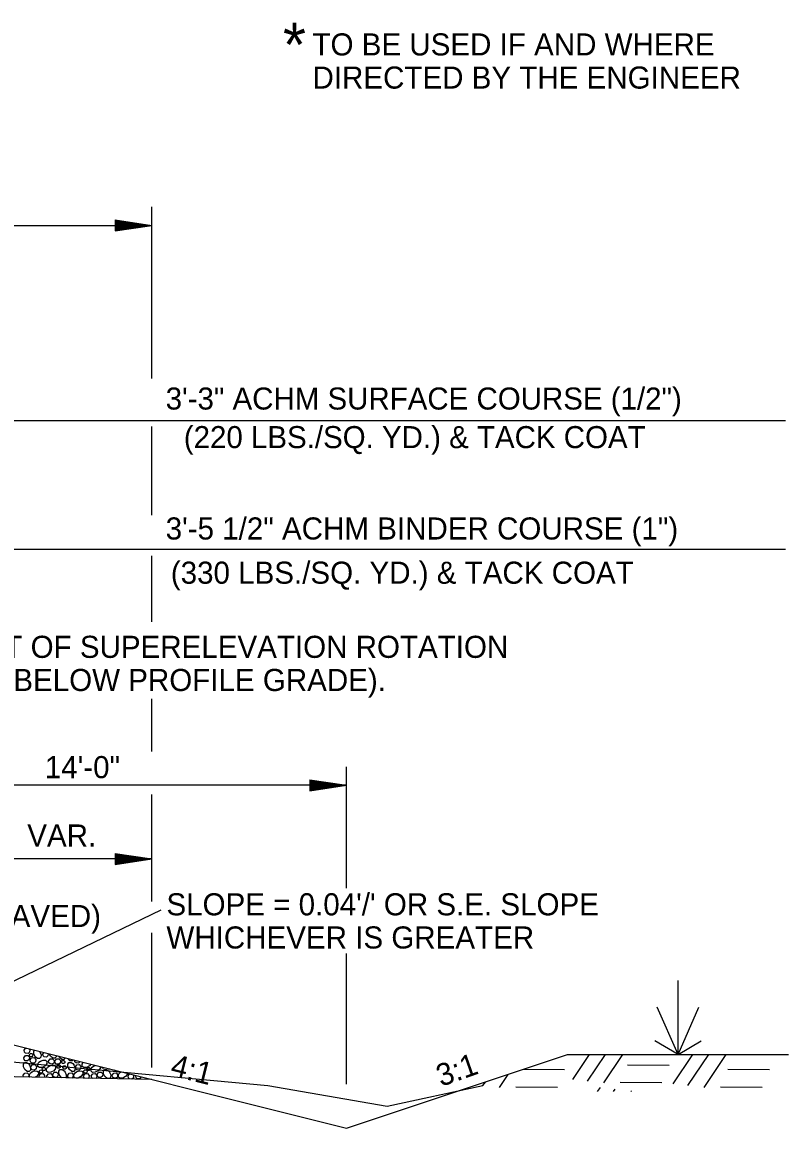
# Model space of a CAD drawing. Extents: x 2478 to 3210, y 439 to 841.
# Drawn here: x 3063.6 to 3105.2, y 779.4 to 840.5 of the extents above; entities that cross this region are included whole.
import ezdxf

# ---------------------------------------------------------------- set-up
doc = ezdxf.new("R2010")
doc.units = 0
for name, color, linetype in [('R_Annotation', 7, 'Continuous'), ('R_Dimension', 7, 'Continuous'), ('R_Draft', 7, 'Continuous'), ('R_Exist Surface', 7, 'Continuous')]:
    doc.layers.add(name, color=color, linetype=linetype)

msp = doc.modelspace()

# ---------------------------------------------------------------- linework, layer by layer
at = {"layer": 'R_Annotation'}
for p, q in [((3061.233, 785.503), (3081.233, 780.503)), ((3081.233, 780.503), (3093.233, 784.503)), ((3093.233, 784.503), (3105.233, 784.503)), ((3070.657, 783.147), (3051.233, 783.536))]:
    msp.add_line(p, q, dxfattribs=at)
at = {"layer": 'R_Dimension'}
for p, q in [((3070.657, 821.217), (3070.657, 830.525)), ((3068.657, 829.825), (3070.657, 829.525)), ((3068.657, 829.825), (3068.657, 829.225)), ((3068.657, 829.775), (3070.323, 829.525)), ((3068.657, 829.724), (3069.979, 829.525)), ((3068.657, 829.674), (3069.646, 829.525)), ((3068.657, 829.622), (3069.307, 829.525)), ((2989.723, 829.525), (3070.657, 829.525)), ((3068.657, 829.572), (3068.973, 829.525)), ((3068.657, 829.225), (3070.657, 829.525)), ((3068.657, 829.427), (3069.307, 829.525)), ((3068.657, 829.326), (3069.979, 829.525)), ((3068.657, 829.275), (3070.323, 829.525)), ((3068.657, 829.376), (3069.646, 829.525)), ((3068.657, 829.478), (3068.973, 829.525)), ((3051.233, 818.934), (3105.077, 818.934)), ((3070.657, 813.783), (3070.657, 818.612)), ((3051.233, 811.949), (3105.077, 811.949)), ((3070.657, 807.995), (3070.657, 811.587)), ((3070.657, 800.953), (3070.657, 803.813)), ((3081.233, 793.542), (3081.233, 800.13)), ((3081.233, 799.13), (3053.233, 799.13)), ((3079.233, 799.43), (3081.233, 799.13)), ((3079.233, 799.43), (3079.233, 798.83)), ((3079.233, 799.38), (3080.899, 799.13)), ((3079.233, 799.329), (3080.555, 799.13)), ((3079.233, 799.279), (3080.222, 799.13)), ((3079.233, 799.227), (3079.883, 799.13)), ((3079.233, 799.177), (3079.549, 799.13)), ((3079.233, 798.83), (3081.233, 799.13)), ((3079.233, 799.032), (3079.883, 799.13)), ((3079.233, 798.931), (3080.555, 799.13)), ((3079.233, 798.88), (3080.899, 799.13)), ((3079.233, 798.981), (3080.222, 799.13)), ((3079.233, 799.083), (3079.549, 799.13)), ((3070.657, 792.825), (3070.657, 798.63)), ((3068.657, 795.43), (3070.657, 795.13)), ((3068.657, 795.43), (3068.657, 794.83)), ((3068.657, 795.38), (3070.323, 795.13)), ((3068.657, 795.329), (3069.979, 795.13)), ((3070.657, 795.13), (2989.723, 795.13)), ((3068.657, 795.279), (3069.646, 795.13)), ((3068.657, 795.227), (3069.307, 795.13)), ((3068.657, 795.177), (3068.973, 795.13)), ((3068.657, 794.83), (3070.657, 795.13)), ((3068.657, 795.032), (3069.307, 795.13)), ((3068.657, 794.931), (3069.979, 795.13)), ((3068.657, 794.88), (3070.323, 795.13)), ((3068.657, 794.981), (3069.646, 795.13)), ((3068.657, 795.083), (3068.973, 795.13)), ((3057.233, 785.663), (3071.157, 792.365)), ((3070.657, 783.814), (3070.657, 791.119)), ((3081.233, 782.901), (3081.233, 789.988)), ((3064.561, 784.671), (3064.583, 784.643)), ((3064.723, 784.533), (3064.781, 784.616)), ((3093.516, 783.153), (3094.426, 784.503)), ((3094.313, 783.061), (3095.286, 784.503)), ((3095.203, 782.968), (3096.239, 784.503)), ((3098.966, 782.912), (3100.04, 784.503)), ((3099.764, 782.82), (3100.9, 784.503)), ((3100.654, 782.727), (3101.852, 784.503)), ((3067.478, 783.873), (3067.586, 783.915)), ((3090.852, 783.71), (3093.071, 783.691)), ((3096.482, 783.951), (3098.744, 783.933)), ((3101.933, 783.71), (3104.195, 783.691)), ((3064.547, 783.27), (3064.528, 783.338)), ((3064.971, 783.261), (3064.948, 783.353)), ((3068.963, 783.563), (3068.975, 783.568)), ((3069.358, 783.353), (3069.435, 783.453)), ((3069.778, 783.353), (3069.787, 783.365)), ((3070.644, 783.148), (3070.649, 783.149)), ((3089.53, 782.727), (3090.001, 783.426)), ((3088.64, 782.82), (3088.772, 783.016)), ((3090.419, 782.764), (3092.681, 782.745)), ((3094.867, 782.503), (3095.017, 782.727)), ((3095.727, 782.503), (3095.815, 782.634)), ((3096.093, 783.005), (3098.355, 782.987)), ((3096.679, 782.503), (3096.705, 782.541)), ((3101.544, 782.764), (3103.805, 782.745))]:
    msp.add_line(p, q, dxfattribs=at)
for points in [[(3063.703, 784.333), (3063.783, 784.453), (3063.908, 784.458), (3064.003, 784.358), (3063.993, 784.233), (3063.903, 784.163), (3063.778, 784.168), (3063.718, 784.233), (3063.703, 784.333)], [(3063.723, 784.738), (3063.798, 784.848), (3063.841, 784.851)], [(3063.974, 784.818), (3064.023, 784.763), (3064.013, 784.633), (3063.928, 784.568), (3063.798, 784.578), (3063.738, 784.633), (3063.723, 784.738)], [(3064.003, 784.498), (3064.048, 784.568), (3064.128, 784.573), (3064.183, 784.518), (3064.178, 784.438), (3064.128, 784.393), (3064.048, 784.403), (3064.013, 784.438), (3064.003, 784.498)], [(3064.043, 784.213), (3064.123, 784.333), (3064.258, 784.343), (3064.343, 784.243), (3064.328, 784.113), (3064.253, 784.048), (3064.123, 784.053), (3064.063, 784.113), (3064.043, 784.213)], [(3064.573, 784.648), (3064.638, 784.498), (3064.623, 784.358), (3064.558, 784.293), (3064.448, 784.298), (3064.318, 784.393), (3064.243, 784.548), (3064.238, 784.698), (3064.273, 784.743)], [(3065.026, 784.555), (3065.008, 784.438), (3064.933, 784.373), (3064.803, 784.378), (3064.743, 784.438), (3064.723, 784.533)], [(3065.461, 784.446), (3065.453, 784.378), (3065.388, 784.308), (3065.273, 784.318), (3065.148, 784.418), (3065.081, 784.541)], [(3065.935, 784.328), (3065.933, 784.303), (3065.873, 784.238), (3065.758, 784.243), (3065.633, 784.343), (3065.595, 784.413)], [(3064.008, 783.938), (3064.068, 783.793), (3064.058, 783.653), (3063.998, 783.583), (3063.883, 783.583), (3063.758, 783.688), (3063.673, 783.843), (3063.673, 783.988), (3063.728, 784.078), (3063.848, 784.083), (3063.953, 784.018), (3064.013, 783.933)], [(3064.083, 783.838), (3064.158, 783.953), (3064.288, 783.963), (3064.383, 783.863), (3064.368, 783.733), (3064.283, 783.668), (3064.158, 783.673), (3064.098, 783.733), (3064.083, 783.838)], [(3064.598, 784.148), (3064.748, 784.208), (3064.883, 784.198), (3064.948, 784.138), (3064.948, 784.023), (3064.853, 783.893), (3064.693, 783.813), (3064.548, 783.813), (3064.458, 783.868), (3064.453, 783.983), (3064.523, 784.093), (3064.603, 784.153)], [(3064.703, 783.743), (3064.753, 783.808), (3064.828, 783.813), (3064.883, 783.758), (3064.878, 783.683), (3064.828, 783.638), (3064.753, 783.648), (3064.718, 783.683), (3064.703, 783.743)], [(3065.063, 783.873), (3065.218, 783.933), (3065.358, 783.923), (3065.423, 783.863), (3065.423, 783.748), (3065.323, 783.618), (3065.163, 783.543), (3065.013, 783.538), (3064.933, 783.598), (3064.928, 783.718), (3064.993, 783.818), (3065.073, 783.878)], [(3065.048, 784.158), (3065.123, 784.273), (3065.258, 784.278), (3065.353, 784.188), (3065.338, 784.053), (3065.253, 783.988), (3065.123, 783.998), (3065.063, 784.053), (3065.048, 784.158)], [(3065.378, 784.153), (3065.468, 784.268), (3065.593, 784.278), (3065.688, 784.183), (3065.668, 784.048), (3065.593, 783.983), (3065.463, 783.993), (3065.408, 784.053), (3065.378, 784.153)], [(3065.498, 783.873), (3065.548, 783.943), (3065.633, 783.943), (3065.688, 783.893), (3065.668, 783.813), (3065.623, 783.773), (3065.548, 783.778), (3065.518, 783.813), (3065.498, 783.873)], [(3065.753, 784.113), (3065.808, 784.188), (3065.878, 784.188), (3065.933, 784.138), (3065.928, 784.053), (3065.878, 784.023), (3065.798, 784.028), (3065.763, 784.053), (3065.753, 784.113)], [(3065.823, 783.813), (3065.873, 783.888), (3065.953, 783.893), (3066.003, 783.838), (3065.993, 783.753), (3065.943, 783.718), (3065.873, 783.723), (3065.833, 783.753), (3065.823, 783.813)], [(3066.423, 783.938), (3066.483, 783.793), (3066.473, 783.653), (3066.413, 783.583), (3066.298, 783.583), (3066.173, 783.688), (3066.088, 783.843), (3066.088, 783.988), (3066.143, 784.078), (3066.263, 784.083), (3066.368, 784.018), (3066.428, 783.933)], [(3066.385, 784.215), (3066.318, 784.163), (3066.193, 784.168), (3066.133, 784.233), (3066.126, 784.28)], [(3066.745, 784.125), (3066.743, 784.113), (3066.668, 784.048), (3066.538, 784.053), (3066.478, 784.113), (3066.462, 784.196)], [(3066.498, 783.838), (3066.573, 783.953), (3066.703, 783.963), (3066.798, 783.863), (3066.783, 783.733), (3066.698, 783.668), (3066.573, 783.673), (3066.513, 783.733), (3066.498, 783.838)], [(3067.331, 783.979), (3067.268, 783.893), (3067.108, 783.813), (3066.963, 783.813), (3066.873, 783.868), (3066.868, 783.983), (3066.929, 784.079)], [(3067.118, 783.743), (3067.168, 783.808), (3067.243, 783.813), (3067.298, 783.758), (3067.293, 783.683), (3067.243, 783.638), (3067.168, 783.648), (3067.133, 783.683), (3067.118, 783.743)], [(3067.838, 783.852), (3067.838, 783.748), (3067.738, 783.618), (3067.578, 783.543), (3067.428, 783.538), (3067.348, 783.598), (3067.343, 783.718), (3067.408, 783.818), (3067.488, 783.878)], [(3068.064, 783.796), (3068.038, 783.773), (3067.963, 783.778), (3067.933, 783.813), (3067.928, 783.83)], [(3068.362, 783.721), (3068.358, 783.718), (3068.288, 783.723), (3068.256, 783.748)], [(3063.668, 783.388), (3063.753, 783.503), (3063.883, 783.508), (3063.963, 783.418), (3063.953, 783.288), (3063.946, 783.282)], [(3063.685, 783.287), (3063.683, 783.288), (3063.668, 783.388)], [(3064.019, 783.28), (3064.008, 783.288), (3064.003, 783.403), (3064.068, 783.508), (3064.143, 783.573)], [(3064.133, 783.563), (3064.283, 783.623), (3064.428, 783.613), (3064.498, 783.553), (3064.493, 783.438), (3064.388, 783.313), (3064.315, 783.274)], [(3064.528, 783.353), (3064.613, 783.463), (3064.743, 783.473), (3064.828, 783.373), (3064.82, 783.264)], [(3064.533, 783.603), (3064.583, 783.668), (3064.663, 783.673), (3064.718, 783.618), (3064.708, 783.538), (3064.663, 783.498), (3064.583, 783.503), (3064.548, 783.543), (3064.533, 783.603)], [(3064.948, 783.353), (3065.033, 783.463), (3065.163, 783.478), (3065.253, 783.378), (3065.234, 783.256)], [(3065.268, 783.433), (3065.343, 783.548), (3065.478, 783.558), (3065.573, 783.463), (3065.553, 783.333), (3065.473, 783.268), (3065.343, 783.273), (3065.283, 783.333), (3065.268, 783.433)], [(3065.766, 783.245), (3065.688, 783.308), (3065.608, 783.453), (3065.603, 783.608), (3065.663, 783.688), (3065.778, 783.698), (3065.888, 783.633), (3065.953, 783.553)], [(3065.943, 783.558), (3066.003, 783.413), (3065.993, 783.268), (3065.968, 783.241)], [(3066.083, 783.388), (3066.168, 783.503), (3066.298, 783.508), (3066.378, 783.418), (3066.368, 783.288), (3066.31, 783.234)], [(3066.158, 783.237), (3066.098, 783.288), (3066.083, 783.388)], [(3066.5, 783.23), (3066.423, 783.288), (3066.418, 783.403), (3066.483, 783.508), (3066.558, 783.573)], [(3066.548, 783.563), (3066.698, 783.623), (3066.843, 783.613), (3066.913, 783.553), (3066.908, 783.438), (3066.803, 783.313), (3066.653, 783.233), (3066.543, 783.23)], [(3066.943, 783.353), (3067.028, 783.463), (3067.158, 783.473), (3067.243, 783.373), (3067.233, 783.248), (3067.199, 783.216)], [(3066.994, 783.221), (3066.968, 783.248), (3066.943, 783.338)], [(3066.948, 783.603), (3066.998, 783.668), (3067.078, 783.673), (3067.133, 783.618), (3067.123, 783.538), (3067.078, 783.498), (3066.998, 783.503), (3066.963, 783.543), (3066.948, 783.603)], [(3067.363, 783.353), (3067.448, 783.463), (3067.578, 783.478), (3067.668, 783.378), (3067.648, 783.248), (3067.602, 783.208)], [(3067.43, 783.212), (3067.388, 783.253), (3067.363, 783.353)], [(3067.683, 783.433), (3067.758, 783.548), (3067.893, 783.558), (3067.988, 783.463), (3067.968, 783.333), (3067.888, 783.268), (3067.758, 783.273), (3067.698, 783.333), (3067.683, 783.433)], [(3068.358, 783.558), (3068.418, 783.413), (3068.408, 783.268), (3068.348, 783.203), (3068.233, 783.203), (3068.103, 783.308), (3068.023, 783.453), (3068.018, 783.608), (3068.078, 783.688), (3068.193, 783.698), (3068.303, 783.633), (3068.368, 783.553)], [(3068.498, 783.388), (3068.583, 783.503), (3068.713, 783.508), (3068.793, 783.418), (3068.783, 783.288), (3068.708, 783.218), (3068.583, 783.228), (3068.513, 783.288), (3068.498, 783.388)], [(3068.843, 783.601), (3068.828, 783.583), (3068.713, 783.583), (3068.629, 783.654)], [(3069.325, 783.48), (3069.323, 783.438), (3069.218, 783.313), (3069.068, 783.233), (3068.918, 783.228), (3068.838, 783.288), (3068.833, 783.403), (3068.898, 783.508), (3068.969, 783.569)], [(3069.633, 783.403), (3069.658, 783.373), (3069.648, 783.248), (3069.573, 783.178), (3069.443, 783.183), (3069.383, 783.248), (3069.358, 783.338)], [(3070.07, 783.294), (3070.063, 783.248), (3069.988, 783.183), (3069.863, 783.193), (3069.803, 783.253), (3069.778, 783.353)]]:
    msp.add_lwpolyline(points, dxfattribs=at)
at = {"layer": 'R_Draft'}
for q in [(3099.233, 788.521), (3098.095, 787.089), (3100.372, 787.089), (3097.975, 785.261), (3100.492, 785.261)]:
    msp.add_line((3099.233, 784.503), q, dxfattribs=at)
at = {"layer": 'R_Exist Surface'}
msp.add_lwpolyline([(2974.394, 779.542), (2980.464, 779.356), (2991.6, 780.578), (3008.322, 785.91), (3009.233, 786.036), (3031.233, 785.919), (3053.233, 785.156), (3055.82, 784.789), (3076.957, 782.83), (3083.428, 781.714), (3088.64, 782.82)], dxfattribs=at)

# ---------------------------------------------------------------- texts
at = {"layer": 'R_Annotation'}
for s, height, p in [('*', 2.4, (3077.774, 838.135)), ('TO BE USED IF AND WHERE ', 1.2, (3079.378, 838.748)), ('DIRECTED BY THE ENGINEER', 1.2, (3079.378, 836.948)), ('3\'-3" ACHM SURFACE COURSE (1/2")', 1.197, (3071.404, 819.524)), ('(220 LBS./SQ. YD.) & TACK COAT', 1.197, (3072.389, 817.429)), ('3\'-5 1/2" ACHM BINDER COURSE (1")', 1.2, (3071.404, 812.468)), ('(330 LBS./SQ. YD.) & TACK COAT', 1.2, (3071.683, 810.068)), ('POINT OF SUPERELEVATION ROTATION ', 1.2, (3058.719, 806.043)), ("(0.22' BELOW PROFILE GRADE).", 1.2, (3058.719, 804.243)), ('14\'-0"', 1.2, (3064.838, 799.512)), ('VAR.', 1.2, (3063.886, 795.8)), ("SLOPE = 0.04'/' OR S.E. SLOPE", 1.2, (3071.446, 792.064)), ("2' (PAVED)", 1.2, (3059.737, 791.428)), ('WHICHEVER IS GREATER', 1.2, (3071.446, 790.264))]:
    msp.add_text(s, height=height, dxfattribs=at).set_placement(p)
for s, rotation, p in [('4:1', 345.964, (3071.603, 783.383)), ('3:1', 19.33935, (3086.36, 782.751))]:
    msp.add_text(s, height=1.2, rotation=rotation, dxfattribs=at).set_placement(p)

doc.saveas('drawing.dxf')
